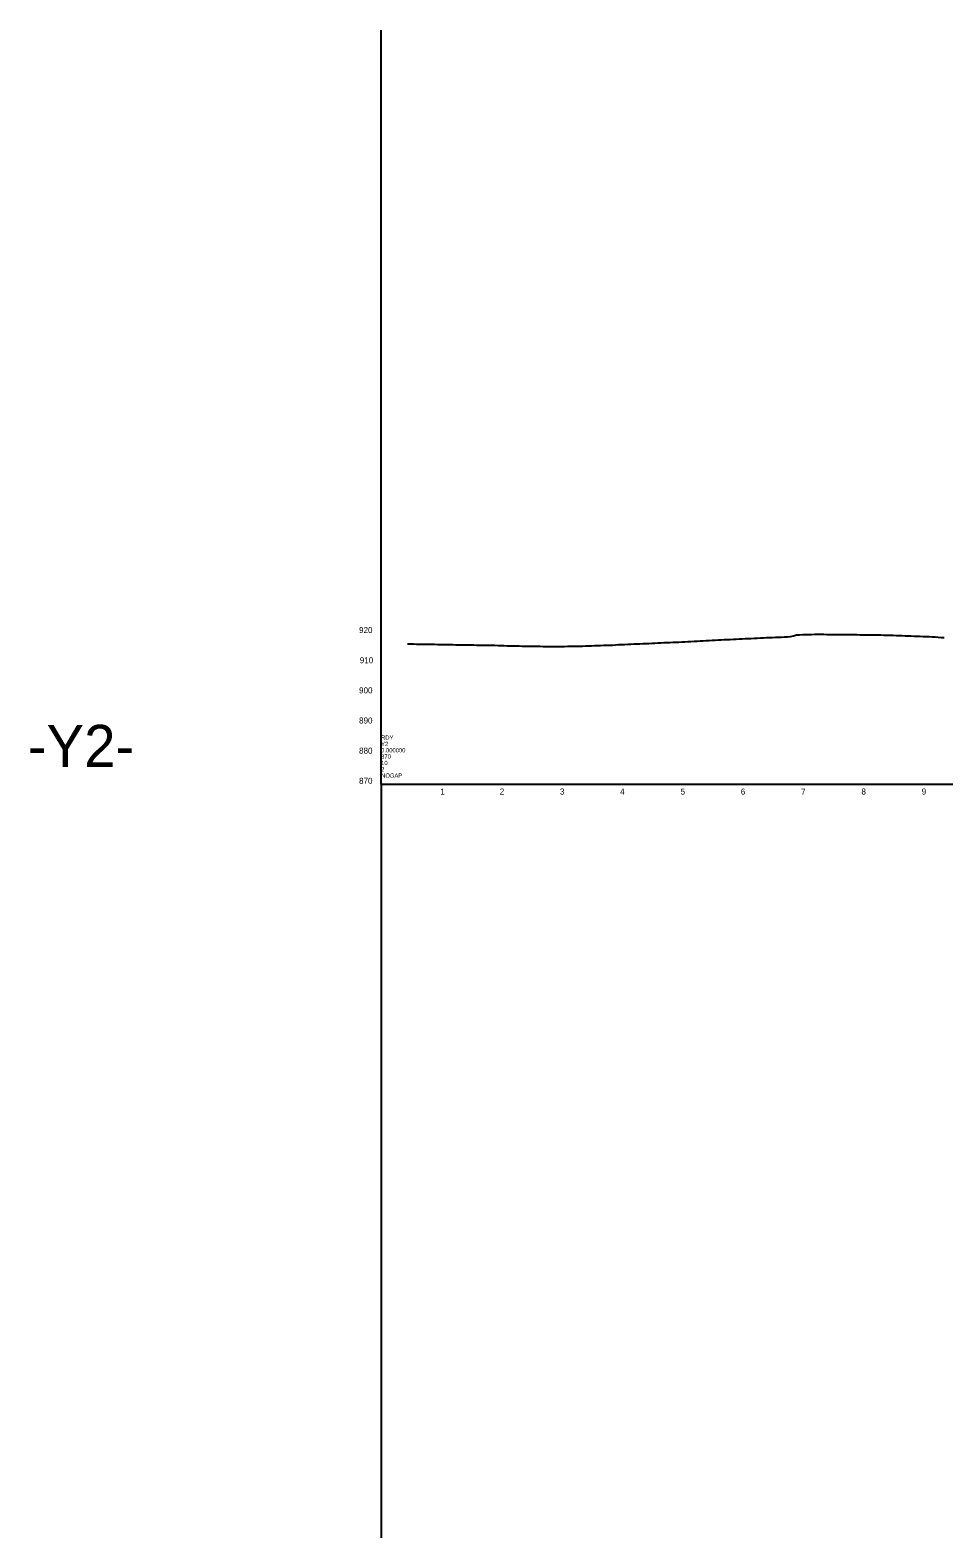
# Model space of a CAD drawing. Extents: x 1645136 to 1655379, y 764766 to 852516.
# Drawn here: x 1648497 to 1650012, y 826016 to 828516 of the extents above; entities that cross this region are included whole.
import ezdxf

# ---------------------------------------------------------------- set-up
doc = ezdxf.new("R2010")
doc.units = 0
for name, color, linetype in [('Default', 7, 'Continuous'), ('Exist Profile Cell', 7, 'Continuous'), ('Exist Vertical Profile Ground Line', 7, 'Continuous'), ('Exist Vertical Profile Horizontal Axis Label Major', 7, 'Continuous'), ('Exist Vertical Profile Vertical Axis Label', 7, 'Continuous')]:
    doc.layers.add(name, color=color, linetype=linetype)

msp = doc.modelspace()

# ---------------------------------------------------------------- linework, layer by layer
at = {"layer": 'Default'}
msp.add_line((1649079.3, 827266), (1649079.3, 826016), dxfattribs=at)
at = {"layer": 'Exist Profile Cell'}
for q in [(1649079.3, 828516), (1651079.3, 827266), (1649079.3, 826016)]:
    msp.add_line((1649079.3, 827266), q, dxfattribs=at)
at = {"layer": 'Exist Vertical Profile Ground Line'}
for points in [[(1649123.1, 827498.5), (1649128.1, 827498.4), (1649133.1, 827498.2), (1649138.1, 827498), (1649143.1, 827497.9), (1649148.1, 827497.8), (1649153.1, 827497.7), (1649158.1, 827497.7), (1649163.1, 827497.7), (1649168.1, 827497.7), (1649173.1, 827497.6), (1649178.1, 827497.5), (1649183.1, 827497.4), (1649188.1, 827497.2), (1649193.1, 827497.1), (1649198.1, 827497.2), (1649203.1, 827497), (1649208.1, 827497), (1649213.1, 827496.9), (1649218.1, 827496.8), (1649223.1, 827496.9), (1649228.1, 827496.7), (1649233.1, 827496.6), (1649238.1, 827496.5), (1649243.1, 827496.4), (1649248.1, 827496.4), (1649253.1, 827496.3), (1649258.1, 827496.2), (1649263.1, 827496.1), (1649268.1, 827496), (1649273.1, 827495.8), (1649278.1, 827495.7), (1649283.1, 827495.5), (1649288.1, 827495.4), (1649293.1, 827495.4), (1649298.1, 827495.2), (1649303.1, 827495.1), (1649308.1, 827494.9), (1649313.1, 827494.8), (1649318.1, 827494.7), (1649323.1, 827494.6), (1649328.1, 827494.6), (1649333.1, 827494.4), (1649338.1, 827494.3), (1649343.1, 827494.3), (1649348.1, 827494.2), (1649353.1, 827494.1), (1649358.1, 827494.1), (1649363.1, 827494), (1649368.1, 827494), (1649373.1, 827494), (1649378.1, 827494.1), (1649383.1, 827494.2), (1649388.1, 827494.3), (1649393.1, 827494.3), (1649398.1, 827494.3), (1649403.1, 827494.4), (1649408.1, 827494.6), (1649413.1, 827494.7), (1649418.1, 827494.9), (1649423.1, 827495.1), (1649428.1, 827495.2), (1649433.1, 827495.5), (1649438.1, 827495.6), (1649443.1, 827495.8), (1649448.1, 827496), (1649453.1, 827496.2), (1649458.1, 827496.3), (1649463.1, 827496.5), (1649468.1, 827496.8), (1649473.1, 827497.1), (1649478.1, 827497.3), (1649483.1, 827497.5), (1649488.1, 827497.7), (1649493.1, 827498), (1649498.1, 827498.3), (1649503.1, 827498.6), (1649508.1, 827498.7), (1649513.1, 827498.9), (1649518.1, 827499.1), (1649523.1, 827499.2), (1649528.1, 827499.4), (1649533.1, 827499.7), (1649538.1, 827499.9), (1649543.1, 827500.1), (1649548.1, 827500.4), (1649553.1, 827500.6), (1649558.1, 827500.8), (1649563.1, 827501), (1649568.1, 827501.2), (1649573.1, 827501.4), (1649578.1, 827501.7), (1649583.1, 827501.8), (1649588.1, 827502.1), (1649593.1, 827502.3), (1649598.1, 827502.6), (1649603.1, 827502.9), (1649608.1, 827503.2), (1649613.1, 827503.5), (1649618.1, 827503.8), (1649623.1, 827504.1)], [(1649623.1, 827504.1), (1649628.1, 827504.4), (1649633.1, 827504.7), (1649638.1, 827505), (1649643.1, 827505.2), (1649648.1, 827505.4), (1649653.1, 827505.6), (1649658.1, 827505.8), (1649663.1, 827506.1), (1649668.1, 827506.4), (1649673.1, 827506.7), (1649678.1, 827506.9), (1649683.1, 827507.2), (1649688.1, 827507.4), (1649693.1, 827507.5), (1649698.1, 827507.8), (1649703.1, 827508), (1649708.1, 827508.3), (1649713.1, 827508.5), (1649718.1, 827508.7), (1649723.1, 827508.9), (1649728.1, 827509.1), (1649733.1, 827509.4), (1649738.1, 827509.5), (1649743.1, 827509.7), (1649748.1, 827509.9), (1649753.1, 827510.2), (1649758.1, 827510.4), (1649763.1, 827511.8), (1649768.1, 827513.2), (1649773.1, 827513.4), (1649778.1, 827513.7), (1649783.1, 827513.7), (1649788.1, 827513.9), (1649793.1, 827514.1), (1649798.1, 827514.3), (1649803.1, 827514.6), (1649808.1, 827514.5), (1649813.1, 827514.7), (1649818.1, 827513.8), (1649823.1, 827513.7), (1649828.1, 827513.8), (1649833.1, 827513.8), (1649838.1, 827513.7), (1649843.1, 827513.7), (1649848.1, 827513.7), (1649853.1, 827513.7), (1649858.1, 827513.7), (1649863.1, 827513.7), (1649868.1, 827513.7), (1649873.1, 827513.6), (1649878.1, 827513.6), (1649883.1, 827513.5), (1649888.1, 827513.5), (1649893.1, 827513.5), (1649898.1, 827513.4), (1649903.1, 827513.3), (1649908.1, 827513.2), (1649913.1, 827513), (1649918.1, 827512.9), (1649923.1, 827512.8), (1649928.1, 827512.6), (1649933.1, 827512.4), (1649938.1, 827512.2), (1649943.1, 827512), (1649948.1, 827511.8), (1649953.1, 827511.7), (1649958.1, 827511.5), (1649963.1, 827511.4), (1649968.1, 827511.2), (1649973.1, 827511), (1649978.1, 827510.8), (1649983.1, 827510.7), (1649988.1, 827510.4), (1649993.1, 827510.1), (1649998.1, 827509.9), (1650003.1, 827509.6), (1650008.1, 827509.2), (1650013.1, 827508.8)]]:
    msp.add_lwpolyline(points, dxfattribs=at)

# ---------------------------------------------------------------- texts
at = {"layer": 'Exist Profile Cell'}
for s, height, p in [('-Y2-', 70, (1648493.2, 827294.1)), ('Y2', 7, (1649079.3, 827329)), ('0.000000', 7, (1649079.3, 827318.5)), ('RDY', 7, (1649079.3, 827339.5)), ('870', 7, (1649079.3, 827308)), ('10', 7, (1649079.3, 827297.5)), ('2', 7, (1649079.3, 827287)), ('NOGAP', 7, (1649079.3, 827276.5))]:
    msp.add_text(s, height=height, dxfattribs=at).set_placement(p)
at = {"layer": 'Exist Vertical Profile Horizontal Axis Label Major'}
for s, p in [('1', (1649177.5, 827248.5)), ('2', (1649276, 827248.5)), ('3', (1649375.8, 827248.5)), ('4', (1649475.7, 827248.5)), ('5', (1649575.8, 827248.5)), ('6', (1649675.7, 827248.5)), ('7', (1649775.6, 827248.5)), ('8', (1649875.7, 827248.5)), ('9', (1649975.7, 827248.5))]:
    msp.add_text(s, height=10, dxfattribs=at).set_placement(p)
at = {"layer": 'Exist Vertical Profile Vertical Axis Label'}
for s, p in [('920', (1649042.7, 827516.3)), ('910', (1649043.9, 827466.3)), ('900', (1649042.7, 827416.3)), ('890', (1649042.7, 827366.3)), ('880', (1649042.7, 827316.3)), ('870', (1649042.7, 827266.3))]:
    msp.add_text(s, height=10, dxfattribs=at).set_placement(p)

doc.saveas('drawing.dxf')
